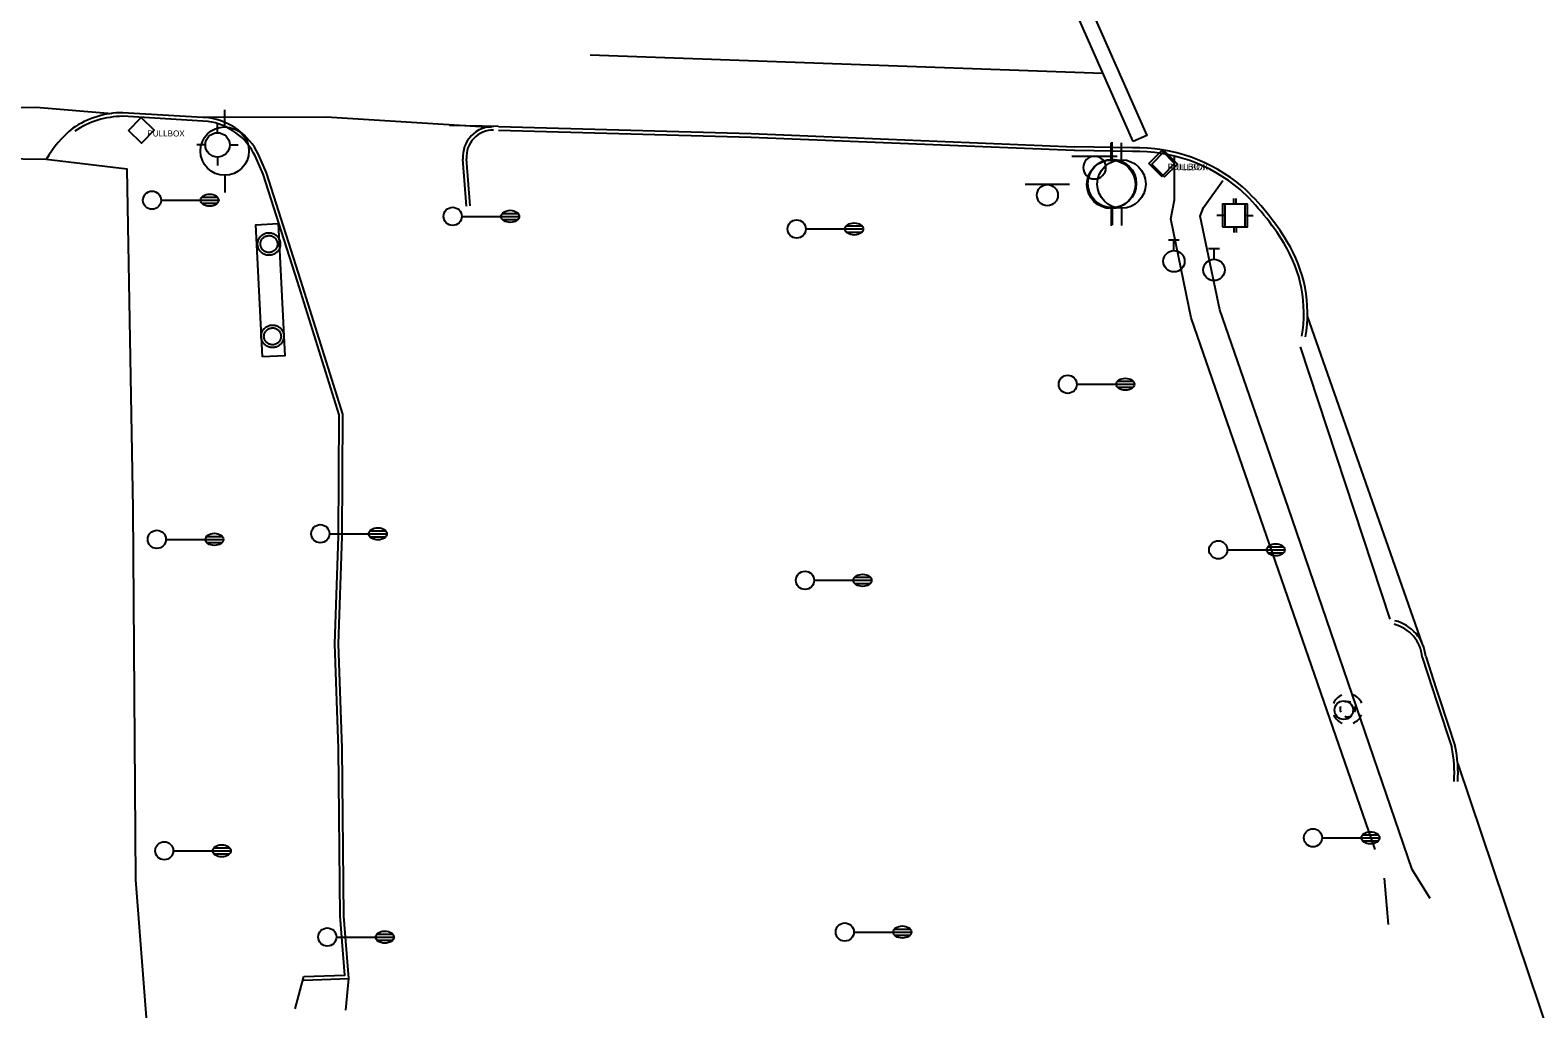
# Model space of a CAD drawing. Extents: x 2145380 to 2157287, y 139568 to 149130.
# Drawn here: x 2147143.4 to 2147392.4, y 142769.3 to 142930.9 of the extents above; entities that cross this region are included whole.
import ezdxf

# ---------------------------------------------------------------- set-up
doc = ezdxf.new("R2010")
doc.units = 0
for name, color, linetype in [('Default', 7, 'Continuous'), ('TOPO_Asphalt', 7, 'Continuous'), ('TOPO_Concrete', 7, 'Continuous'), ('TOPO_Curb Back', 7, 'Continuous'), ('TOPO_DRAIN_Manhole', 7, 'Continuous'), ('TOPO_Light Pole', 7, 'Continuous'), ('TOPO_Misc Line', 7, 'Continuous'), ('TOPO_Power Pole', 7, 'Continuous'), ('TOPO_Power Pullbox', 7, 'Continuous'), ('TOPO_Sign', 7, 'Continuous'), ('TOPO_Traffic Signal', 7, 'Continuous'), ('TOPO_Water Fire Hydrant', 7, 'Continuous'), ('TOPO_Water Meter', 7, 'Continuous'), ('TOPO_Water Valve', 7, 'Continuous')]:
    doc.layers.add(name, color=color, linetype=linetype)

# ---------------------------------------------------------------- blocks, each defined once
blk = doc.blocks.new('TRFSIG')
at = {"layer": 'TOPO_Traffic Signal'}
for p, q in [((0.04, 4.66), (0.04, 7.04)), ((-4.7, -0.09), (-7.08, -0.09)), ((0.04, -4.83), (0.04, -7.22)), ((4.79, -0.09), (7.17, -0.09))]:
    blk.add_line(p, q, dxfattribs=at)
blk.add_lwpolyline([(-4.7, -4.85), (4.81, -4.83), (4.79, 4.67), (-4.72, 4.66), (-4.7, -4.85)], dxfattribs=at)
blk = doc.blocks.new('LP')
at = {"layer": 'TOPO_Light Pole'}
blk.add_line((3.81, 0), (20.32, 0), dxfattribs=at)
for points in [[(20.32, 0), (27.94, 0)], [(20.32, 0), (23.5, 0)], [(20.83, 1.27), (27.43, 1.27)], [(20.83, 1.27), (23.5, 1.27)], [(23.71, 1.27), (27.43, 1.27)], [(23.71, 0), (27.94, 0)], [(20.83, -1.27), (27.43, -1.27)], [(20.83, -1.27), (23.5, -1.27)], [(23.71, -1.27), (27.43, -1.27)]]:
    blk.add_lwpolyline(points, dxfattribs=at)
blk.add_circle((0, 0), 3.81, dxfattribs=at)
blk.add_ellipse((24.13, 0), major_axis=(3.81, 0), ratio=0.666667, dxfattribs=at)
blk = doc.blocks.new('FIRHYD')
at = {"layer": 'TOPO_Water Fire Hydrant'}
for p, q in [((0, 10.2), (0, 17.3)), ((10.2, 0), (17.3, 0)), ((-10.2, 0), (-17.3, 0)), ((0, -10.2), (0, -17.3))]:
    blk.add_line(p, q, dxfattribs=at)
blk.add_circle((0, 0), 10.2, dxfattribs=at)
blk = doc.blocks.new('MHEXST')
at = {"layer": 'TOPO_DRAIN_Manhole'}
for centre, radius, start, end in [((-0.1, 0.3), 12.7, 112.9748, 158.2636), ((-0.1, 0.1), 6.35, 157.9722, 204.161), ((-0.1, 0.1), 6.35, 66.1941, 113.691), ((-0.1, 0.3), 12.7, 22.0744, 68.6991), ((-0.1, 0.1), 6.35, 336.8023, 21.4046), ((-0.1, 0.3), 12.7, 202.6921, 248.1938), ((-0.1, 0.1), 6.35, 248.5791, 293.1995), ((-0.1, 0.3), 12.7, 291.7963, 337.3032)]:
    blk.add_arc(centre, radius, start, end, dxfattribs=at)
blk = doc.blocks.new('pulbox')
at = {"layer": 'Default'}
blk.add_lwpolyline([(-5.38, -0.01), (-0.02, 5.42), (5.4, 0.06), (0.05, -5.36), (-5.38, -0.01)], dxfattribs=at)
blk.add_text('PULLBOX', height=2.54, dxfattribs=at).set_placement((2.54, -2.54))
blk = doc.blocks.new('POWPOL')
at = {"layer": 'TOPO_Power Pole'}
for p, q in [((0, 10.16), (0, 17.34)), ((0, -10.16), (0, -17.34))]:
    blk.add_line(p, q, dxfattribs=at)
blk.add_circle((0, 0), 10.16, dxfattribs=at)
blk = doc.blocks.new('EXSIGN')
at = {"layer": 'Default'}
blk.add_line((9.3, 4.42), (-9.3, 4.42), dxfattribs=at)
blk.add_circle((0, 0), 4.42, dxfattribs=at)
blk = doc.blocks.new('WATVAL')
at = {"layer": 'Default'}
for p, q in [((-2.25, 9), (2.25, 9)), ((0, 4.5), (0, 9))]:
    blk.add_line(p, q, dxfattribs=at)
blk.add_circle((0, 0), 4.5, dxfattribs=at)
blk = doc.blocks.new('WTRMTR')
at = {"layer": 'Default'}
blk.add_circle((0, 0), 3.89, dxfattribs=at)

msp = doc.modelspace()

# ---------------------------------------------------------------- linework, layer by layer
at = {"layer": 'TOPO_Asphalt'}
for p, q in [((2147373.26, 142829.71), (2147354.32, 142883.7)), ((2147379.12, 142809.78), (2147402.56, 142740.4)), ((2147195.56, 142769.14), (2147196.03, 142774.35))]:
    msp.add_line(p, q, dxfattribs=at)
for points in [[(2147129.27, 142918.11), (2147144.44, 142918.24), (2147156.91, 142917.19)], [(2147171.32, 142916.56), (2147192.29, 142916.65), (2147219.6, 142914.91)], [(2147146.08, 142909.6), (2147138.37, 142909.71), (2147135, 142910.15)], [(2147170.58, 142717.59), (2147165.23, 142720.18), (2147164.19, 142747.97), (2147160.9, 142790.64), (2147160.45, 142851.92), (2147159.44, 142907.96), (2147146.08, 142909.6)]]:
    msp.add_lwpolyline(points, dxfattribs=at)
msp.add_arc((2147163.22, 142899.47), 19.91, 129.8624, 149.4159, dxfattribs=at)
at = {"layer": 'TOPO_Concrete'}
msp.add_line((2147187.18, 142769.35), (2147188.59, 142774.69), dxfattribs=at)
for points in [[(2147365.52, 142795.68), (2147346.56, 142850.39), (2147335.14, 142883.45), (2147331.74, 142899.81), (2147332.34, 142902.93), (2147332.34, 142910.02)], [(2147374.59, 142787.58), (2147371.6, 142792.37), (2147351.12, 142852.2), (2147339.84, 142884.76), (2147336.62, 142900.23), (2147337.16, 142901.65), (2147340.35, 142906.09)], [(2147353.09, 142878.63), (2147367.89, 142833.69)], [(2147367.68, 142783.27), (2147367.04, 142790.92)]]:
    msp.add_lwpolyline(points, dxfattribs=at)
at = {"layer": 'TOPO_Curb Back'}
for p, q in [((2147220.78, 142915.02), (2147212.67, 142915.18)), ((2147220.76, 142914.42), (2147262.45, 142913.25)), ((2147220.78, 142915.02), (2147262.47, 142913.85)), ((2147262.44, 142913.25), (2147315.82, 142911.1)), ((2147262.47, 142913.85), (2147315.85, 142911.69)), ((2147215.49, 142901.9), (2147214.89, 142909.65)), ((2147216.09, 142901.94), (2147215.49, 142909.7))]:
    msp.add_line(p, q, dxfattribs=at)
for points in [[(2147172.82, 142915.87), (2147158.73, 142916.71)], [(2147172.88, 142916.47), (2147158.74, 142917.31)], [(2147325.43, 142911.52), (2147315.85, 142911.69)], [(2147188.59, 142774.69), (2147195.38, 142774.93), (2147194.64, 142784.63), (2147194.32, 142812.36), (2147193.75, 142829.61), (2147194.36, 142847.37), (2147194.47, 142867.43), (2147187.57, 142889.44), (2147181.92, 142907.18), (2147180.57, 142910.16)], [(2147188.62, 142774.09), (2147196.03, 142774.35), (2147195.24, 142784.65), (2147194.92, 142812.37), (2147194.35, 142829.61), (2147194.96, 142847.36), (2147195.07, 142867.52), (2147188.14, 142889.62), (2147182.48, 142907.39), (2147181.12, 142910.41)], [(2147325.43, 142910.92), (2147315.92, 142911.09)], [(2147373.24, 142827.41), (2147375.01, 142822.02)], [(2147373.84, 142827.54), (2147375.58, 142822.21)], [(2147375.01, 142822.02), (2147375.63, 142820.14), (2147378.14, 142812.51)], [(2147375.58, 142822.21), (2147376.19, 142820.35), (2147378.72, 142812.67)]]:
    msp.add_lwpolyline(points, dxfattribs=at)
for centre, radius, start, end in [((2147158.83, 142902.35), 14.96, 90.3255, 124.0065), ((2147158.83, 142902.35), 14.36, 90.4027, 124.0065), ((2147171.29, 142905.68), 10.91, 25.7484, 81.6416), ((2147171.29, 142905.68), 10.31, 25.7912, 81.4994), ((2147219.87, 142910.04), 5, 88.9036, 184.4404), ((2147219.87, 142910.04), 4.4, 88.9036, 184.4404), ((2147320.63, 142891.77), 20.49, 103.4865, 103.4865), ((2147325.95, 142884.17), 27.36, 49.8805, 91.0983), ((2147320.63, 142891.77), 19.89, 103.705, 103.9565), ((2147325.95, 142884.17), 26.76, 49.9131, 91.122), ((2147314.3, 142873.71), 42.32, 31.2901, 46.9513), ((2147314.3, 142873.71), 42.92, 31.2919, 46.972), ((2147331.66, 142884.15), 22.06, 350.1984, 31.5491), ((2147331.66, 142884.15), 22.66, 350.1984, 31.5457), ((2147367.19, 142826.94), 6.07, 4.5121, 76.4256), ((2147367.19, 142826.94), 6.67, 5.144, 76.4256), ((2147358.04, 142808.33), 20.53, 356.0048, 11.7491), ((2147358.04, 142808.33), 21.13, 356.0048, 11.8411)]:
    msp.add_arc(centre, radius, start, end, dxfattribs=at)
at = {"layer": 'TOPO_Misc Line'}
msp.add_line((2147235.88, 142926.86), (2147320.55, 142923.83), dxfattribs=at)
msp.add_lwpolyline([(2147325.53, 142912.53), (2147309.91, 142947.95), (2147312.15, 142948.94), (2147327.77, 142913.52)], close=True, dxfattribs=at)
at = {"layer": 'TOPO_Power Pole'}
for points in [[(2147180.98, 142895.63), (2147180.99, 142895.76), (2147181.01, 142895.89), (2147181.03, 142896.01), (2147181.07, 142896.14), (2147181.1, 142896.27), (2147181.15, 142896.39), (2147181.21, 142896.51), (2147181.28, 142896.63), (2147181.36, 142896.74), (2147181.44, 142896.84), (2147181.53, 142896.94), (2147181.62, 142897.03), (2147181.73, 142897.11), (2147181.83, 142897.19), (2147181.95, 142897.26), (2147182.07, 142897.32), (2147182.18, 142897.37), (2147182.31, 142897.41), (2147182.44, 142897.45), (2147182.58, 142897.47), (2147182.71, 142897.49), (2147182.84, 142897.49), (2147182.96, 142897.49), (2147183.09, 142897.48), (2147183.23, 142897.46), (2147183.35, 142897.43), (2147183.48, 142897.39), (2147183.6, 142897.34), (2147183.73, 142897.29), (2147183.84, 142897.22), (2147183.95, 142897.15), (2147184.05, 142897.07), (2147184.15, 142896.98), (2147184.24, 142896.89), (2147184.33, 142896.78), (2147184.41, 142896.67), (2147184.48, 142896.56), (2147184.54, 142896.45), (2147184.59, 142896.32), (2147184.64, 142896.2), (2147184.68, 142896.07), (2147184.71, 142895.94), (2147184.72, 142895.81), (2147184.73, 142895.68), (2147184.73, 142895.55), (2147184.72, 142895.42), (2147184.7, 142895.29), (2147184.67, 142895.16), (2147184.63, 142895.03), (2147184.59, 142894.91), (2147184.53, 142894.79), (2147184.47, 142894.67), (2147184.4, 142894.56), (2147184.32, 142894.45), (2147184.23, 142894.35), (2147184.13, 142894.26), (2147184.04, 142894.18), (2147183.93, 142894.09), (2147183.82, 142894.02), (2147183.7, 142893.96), (2147183.58, 142893.9), (2147183.46, 142893.85), (2147183.33, 142893.82), (2147183.2, 142893.79), (2147183.07, 142893.77), (2147182.94, 142893.76), (2147182.82, 142893.76), (2147182.68, 142893.77), (2147182.55, 142893.78), (2147182.42, 142893.81), (2147182.3, 142893.84), (2147182.17, 142893.89), (2147182.05, 142893.94), (2147181.93, 142894.01), (2147181.82, 142894.07), (2147181.71, 142894.15), (2147181.61, 142894.24), (2147181.51, 142894.33), (2147181.43, 142894.43), (2147181.34, 142894.54), (2147181.27, 142894.64), (2147181.2, 142894.75), (2147181.15, 142894.88), (2147181.09, 142895), (2147181.06, 142895.13), (2147181.03, 142895.25), (2147181.01, 142895.39), (2147180.99, 142895.52), (2147180.98, 142895.63)], [(2147181.45, 142895.63), (2147181.46, 142895.74), (2147181.48, 142895.85), (2147181.5, 142895.96), (2147181.53, 142896.07), (2147181.57, 142896.18), (2147181.62, 142896.29), (2147181.68, 142896.38), (2147181.75, 142896.48), (2147181.82, 142896.56), (2147181.9, 142896.64), (2147181.99, 142896.73), (2147182.08, 142896.79), (2147182.18, 142896.85), (2147182.28, 142896.9), (2147182.38, 142896.94), (2147182.49, 142896.98), (2147182.61, 142897), (2147182.72, 142897.03), (2147182.84, 142897.03), (2147182.95, 142897.03), (2147183.06, 142897.02), (2147183.18, 142896.99), (2147183.28, 142896.96), (2147183.39, 142896.92), (2147183.5, 142896.88), (2147183.59, 142896.82), (2147183.69, 142896.75), (2147183.78, 142896.68), (2147183.86, 142896.61), (2147183.94, 142896.52), (2147184.01, 142896.42), (2147184.07, 142896.33), (2147184.13, 142896.23), (2147184.17, 142896.12), (2147184.21, 142896.01), (2147184.24, 142895.9), (2147184.25, 142895.79), (2147184.26, 142895.68), (2147184.26, 142895.57), (2147184.25, 142895.46), (2147184.23, 142895.34), (2147184.21, 142895.23), (2147184.16, 142895.12), (2147184.12, 142895.02), (2147184.07, 142894.92), (2147184, 142894.82), (2147183.94, 142894.73), (2147183.86, 142894.64), (2147183.78, 142894.56), (2147183.68, 142894.49), (2147183.58, 142894.43), (2147183.49, 142894.37), (2147183.38, 142894.32), (2147183.28, 142894.29), (2147183.16, 142894.26), (2147183.05, 142894.24), (2147182.93, 142894.23), (2147182.83, 142894.23), (2147182.71, 142894.24), (2147182.6, 142894.25), (2147182.48, 142894.27), (2147182.38, 142894.31), (2147182.28, 142894.35), (2147182.17, 142894.4), (2147182.08, 142894.47), (2147181.98, 142894.54), (2147181.89, 142894.61), (2147181.81, 142894.69), (2147181.74, 142894.78), (2147181.67, 142894.88), (2147181.62, 142894.97), (2147181.57, 142895.08), (2147181.53, 142895.19), (2147181.5, 142895.3), (2147181.48, 142895.41), (2147181.46, 142895.52), (2147181.45, 142895.63)], [(2147181.57, 142880.38), (2147181.58, 142880.52), (2147181.59, 142880.65), (2147181.61, 142880.77), (2147181.65, 142880.9), (2147181.69, 142881.03), (2147181.74, 142881.15), (2147181.8, 142881.27), (2147181.86, 142881.39), (2147181.95, 142881.5), (2147182.02, 142881.6), (2147182.11, 142881.7), (2147182.21, 142881.79), (2147182.31, 142881.87), (2147182.42, 142881.95), (2147182.54, 142882.02), (2147182.66, 142882.08), (2147182.77, 142882.13), (2147182.9, 142882.17), (2147183.03, 142882.21), (2147183.16, 142882.23), (2147183.29, 142882.25), (2147183.42, 142882.25), (2147183.55, 142882.25), (2147183.68, 142882.24), (2147183.81, 142882.22), (2147183.94, 142882.19), (2147184.07, 142882.15), (2147184.19, 142882.1), (2147184.31, 142882.05), (2147184.43, 142881.98), (2147184.54, 142881.91), (2147184.64, 142881.83), (2147184.74, 142881.74), (2147184.83, 142881.64), (2147184.92, 142881.54), (2147184.99, 142881.43), (2147185.06, 142881.32), (2147185.13, 142881.21), (2147185.18, 142881.08), (2147185.23, 142880.96), (2147185.26, 142880.83), (2147185.29, 142880.7), (2147185.31, 142880.57), (2147185.31, 142880.43), (2147185.31, 142880.31), (2147185.31, 142880.18), (2147185.28, 142880.05), (2147185.26, 142879.92), (2147185.22, 142879.79), (2147185.17, 142879.67), (2147185.11, 142879.55), (2147185.06, 142879.43), (2147184.98, 142879.32), (2147184.9, 142879.21), (2147184.81, 142879.11), (2147184.72, 142879.02), (2147184.62, 142878.93), (2147184.51, 142878.85), (2147184.41, 142878.78), (2147184.29, 142878.72), (2147184.17, 142878.66), (2147184.05, 142878.61), (2147183.91, 142878.58), (2147183.79, 142878.55), (2147183.66, 142878.53), (2147183.53, 142878.52), (2147183.4, 142878.52), (2147183.27, 142878.53), (2147183.14, 142878.54), (2147183.01, 142878.57), (2147182.88, 142878.6), (2147182.76, 142878.65), (2147182.63, 142878.7), (2147182.51, 142878.77), (2147182.41, 142878.83), (2147182.3, 142878.91), (2147182.19, 142878.99), (2147182.1, 142879.09), (2147182.01, 142879.18), (2147181.93, 142879.29), (2147181.86, 142879.4), (2147181.79, 142879.51), (2147181.73, 142879.64), (2147181.68, 142879.76), (2147181.64, 142879.89), (2147181.61, 142880.01), (2147181.59, 142880.14), (2147181.58, 142880.28), (2147181.57, 142880.38)], [(2147182.04, 142880.38), (2147182.05, 142880.49), (2147182.06, 142880.61), (2147182.08, 142880.72), (2147182.12, 142880.83), (2147182.16, 142880.94), (2147182.21, 142881.04), (2147182.27, 142881.14), (2147182.33, 142881.23), (2147182.41, 142881.32), (2147182.49, 142881.4), (2147182.57, 142881.48), (2147182.67, 142881.55), (2147182.76, 142881.61), (2147182.87, 142881.66), (2147182.97, 142881.7), (2147183.08, 142881.74), (2147183.2, 142881.76), (2147183.31, 142881.78), (2147183.42, 142881.78), (2147183.53, 142881.78), (2147183.64, 142881.78), (2147183.76, 142881.75), (2147183.87, 142881.72), (2147183.97, 142881.68), (2147184.08, 142881.64), (2147184.18, 142881.58), (2147184.27, 142881.51), (2147184.37, 142881.44), (2147184.45, 142881.37), (2147184.52, 142881.28), (2147184.6, 142881.18), (2147184.66, 142881.09), (2147184.71, 142880.98), (2147184.76, 142880.88), (2147184.79, 142880.77), (2147184.82, 142880.66), (2147184.84, 142880.55), (2147184.85, 142880.43), (2147184.85, 142880.33), (2147184.84, 142880.22), (2147184.81, 142880.1), (2147184.79, 142879.99), (2147184.75, 142879.88), (2147184.71, 142879.78), (2147184.66, 142879.68), (2147184.59, 142879.58), (2147184.52, 142879.48), (2147184.44, 142879.4), (2147184.36, 142879.32), (2147184.27, 142879.25), (2147184.17, 142879.19), (2147184.08, 142879.13), (2147183.96, 142879.08), (2147183.86, 142879.04), (2147183.75, 142879.02), (2147183.64, 142878.99), (2147183.52, 142878.98), (2147183.42, 142878.98), (2147183.3, 142878.99), (2147183.19, 142879.01), (2147183.07, 142879.03), (2147182.96, 142879.07), (2147182.86, 142879.11), (2147182.76, 142879.16), (2147182.66, 142879.23), (2147182.57, 142879.29), (2147182.48, 142879.37), (2147182.4, 142879.45), (2147182.32, 142879.54), (2147182.26, 142879.64), (2147182.21, 142879.73), (2147182.16, 142879.83), (2147182.11, 142879.94), (2147182.08, 142880.06), (2147182.06, 142880.17), (2147182.05, 142880.28), (2147182.04, 142880.38)]]:
    msp.add_lwpolyline(points, dxfattribs=at)
at = {"layer": 'TOPO_Sign'}
for points in [[(2147315.42, 142910.11), (2147322.91, 142910.12)], [(2147319.17, 142910.11), (2147319.17, 142910.11)], [(2147317.3, 142908.24), (2147317.3, 142908.24)], [(2147321.04, 142908.24), (2147321.04, 142908.24)], [(2147319.17, 142906.37), (2147319.17, 142906.37)]]:
    msp.add_lwpolyline(points, dxfattribs=at)
msp.add_lwpolyline([(2147181.79, 142876.99), (2147180.68, 142898.8), (2147184.38, 142898.99), (2147185.49, 142877.18)], close=True, dxfattribs=at)
for start, end in [(90, 180), (360, 90), (180, 270), (270, 0)]:
    msp.add_arc((2147319.17, 142908.24), 1.87, start, end, dxfattribs=at)

# ---------------------------------------------------------------- block references
at = {"layer": 'TOPO_DRAIN_Manhole', "xscale": 0.19685000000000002, "yscale": 0.19685000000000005}
msp.add_blockref('MHEXST', (2147360.97, 142818.8), dxfattribs=at)
at = {"layer": 'TOPO_Light Pole', "xscale": 0.39370000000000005, "yscale": 0.3937000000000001}
for p in [(2147163.56, 142902.86), (2147213.19, 142900.19), (2147269.98, 142898.11), (2147314.74, 142872.47), (2147191.34, 142847.79), (2147164.35, 142846.86), (2147339.58, 142845.13), (2147271.36, 142840.1), (2147165.57, 142795.45), (2147355.22, 142797.59), (2147192.49, 142781.2), (2147277.93, 142782.03)]:
    msp.add_blockref('LP', p, dxfattribs=at)
at = {"layer": 'TOPO_Power Pole', "xscale": 0.39370000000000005, "yscale": 0.3937000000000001}
for p in [(2147175.55, 142910.97), (2147321.9, 142905.48), (2147322.06, 142905.62), (2147323.61, 142905.53)]:
    msp.add_blockref('POWPOL', p, dxfattribs=at)
at = {"layer": 'TOPO_Power Pullbox', "xscale": 0.39370000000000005, "yscale": 0.3937000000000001}
for p in [(2147161.78, 142914.38), (2147330.26, 142908.91), (2147330.72, 142908.81)]:
    msp.add_blockref('pulbox', p, dxfattribs=at)
at = {"layer": 'TOPO_Sign', "xscale": 0.39370000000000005, "yscale": 0.3937000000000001}
msp.add_blockref('EXSIGN', (2147311.38, 142903.69), dxfattribs=at)
at = {"layer": 'TOPO_Traffic Signal', "xscale": 0.39370000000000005, "yscale": 0.3937000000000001}
for p in [(2147342.16, 142900.37), (2147342.52, 142900.36)]:
    msp.add_blockref('TRFSIG', p, dxfattribs=at)
at = {"layer": 'TOPO_Water Fire Hydrant', "xscale": 0.19685000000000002, "yscale": 0.19685000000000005}
msp.add_blockref('FIRHYD', (2147174.37, 142911.99), dxfattribs=at)
at = {"layer": 'TOPO_Water Meter', "xscale": 0.39370000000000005, "yscale": 0.3937000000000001}
msp.add_blockref('WTRMTR', (2147360.32, 142818.67), dxfattribs=at)
at = {"layer": 'TOPO_Water Valve', "xscale": 0.39370000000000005, "yscale": 0.3937000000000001}
for p in [(2147332.27, 142892.78), (2147338.89, 142891.35)]:
    msp.add_blockref('WATVAL', p, dxfattribs=at)

doc.saveas('drawing.dxf')
